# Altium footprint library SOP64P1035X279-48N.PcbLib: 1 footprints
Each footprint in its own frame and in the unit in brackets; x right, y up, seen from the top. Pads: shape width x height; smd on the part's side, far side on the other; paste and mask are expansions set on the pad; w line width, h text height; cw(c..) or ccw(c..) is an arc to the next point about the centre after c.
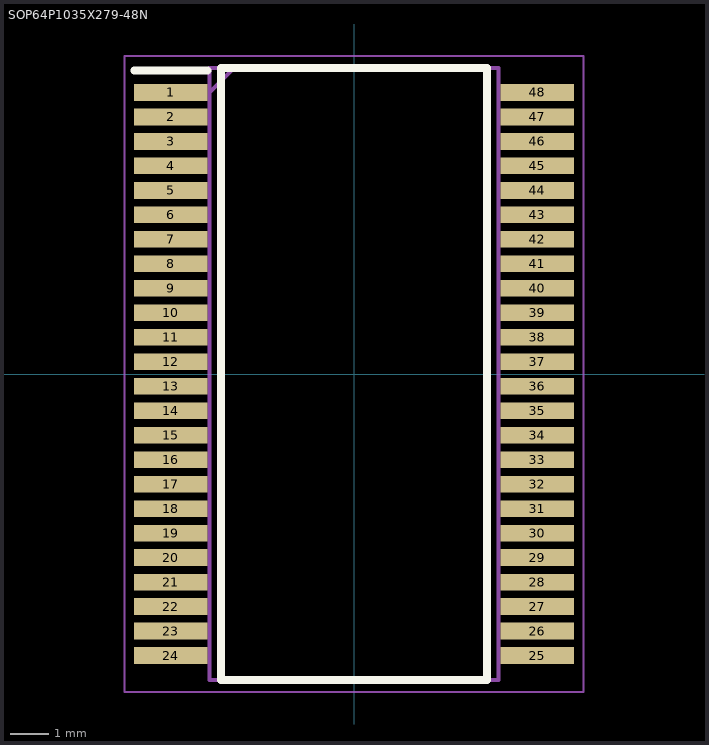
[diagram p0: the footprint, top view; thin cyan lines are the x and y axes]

## SOP64P1035X279-48N [mm]
pads (48):
  rect 1.9x0.435 smd: 1(-4.75,7.302) 2(-4.75,6.668) 3(-4.75,6.032) 4(-4.75,5.398) 5(-4.75,4.762) 6(-4.75,4.128) 7(-4.75,3.492) 8(-4.75,2.858) 9(-4.75,2.222) 10(-4.75,1.588) 11(-4.75,0.952) 12(-4.75,0.318) 13(-4.75,-0.318) 14(-4.75,-0.952) 15(-4.75,-1.588) 16(-4.75,-2.222) 17(-4.75,-2.858) 18(-4.75,-3.492) 19(-4.75,-4.128) 20(-4.75,-4.762) 21(-4.75,-5.398) 22(-4.75,-6.032) 23(-4.75,-6.668) 24(-4.75,-7.302) 25(4.75,-7.302) 26(4.75,-6.668) 27(4.75,-6.032) 28(4.75,-5.398) 29(4.75,-4.762) 30(4.75,-4.128) 31(4.75,-3.492) 32(4.75,-2.858) 33(4.75,-2.222) 34(4.75,-1.588) 35(4.75,-0.952) 36(4.75,-0.318) 37(4.75,0.318) 38(4.75,0.952) 39(4.75,1.588) 40(4.75,2.222) 41(4.75,2.858) 42(4.75,3.492) 43(4.75,4.128) 44(4.75,4.762) 45(4.75,5.398) 46(4.75,6.032) 47(4.75,6.668) 48(4.75,7.302)
Top Overlay:
  lines w0.2: -5.7,7.87 -3.8,7.87 ; -3.45,-7.938 3.45,-7.938 3.45,7.938 -3.45,7.938 -3.45,-7.938
Mechanical 15:
  lines w0.1: -3.745,7.302 -3.11,7.938 ; -3.745,-7.938 3.745,-7.938 3.745,7.938 -3.745,7.938 -3.745,-7.938
Mechanical 20:
  lines w0.05: -5.95,-8.25 5.95,-8.25 5.95,8.25 -5.95,8.25 -5.95,-8.25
